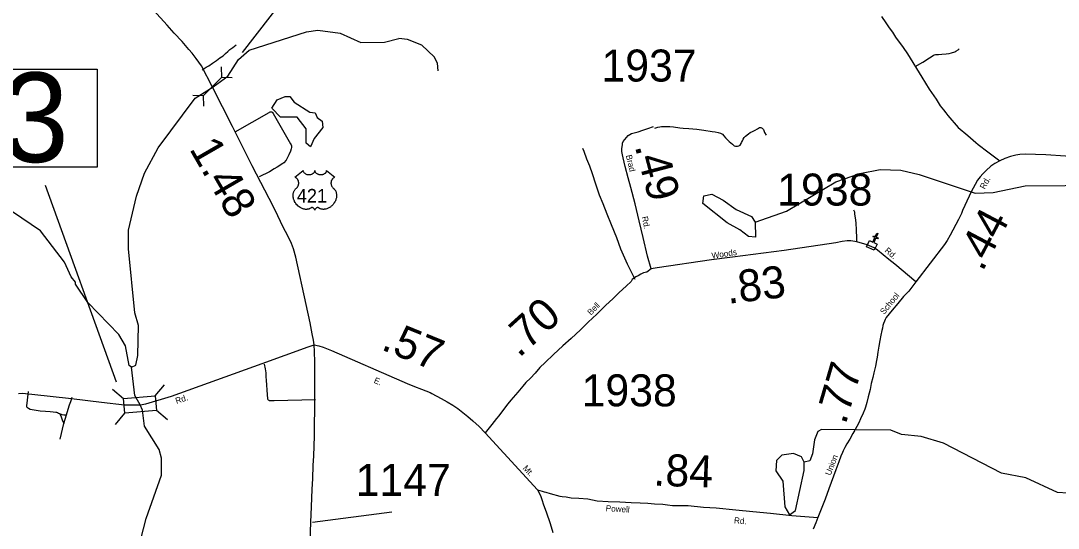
# Model space of a CAD drawing. Extents: x 2093524 to 2270757, y 289120 to 570408.
# Drawn here: x 2218962 to 2235181, y 421724 to 429658 of the extents above; entities that cross this region are included whole.
import ezdxf

# ---------------------------------------------------------------- set-up
doc = ezdxf.new("R2010")
doc.units = 0
for name, color, linetype in [('Exist Cultural Church CELL', 7, 'Continuous'), ('Exist Hydrographic Creek Single Shore', 7, 'Continuous'), ('Exist Hydrographic Misc Water Feature', 7, 'Continuous'), ('Exist Hydrographic Pond Under 1500 Sq Ft', 7, 'Continuous'), ('Exist Road Non-System Type 51', 7, 'Continuous'), ('Exist Road Primary US Attributed', 7, 'Continuous'), ('Exist Road Primary US Mileage Hundredths English Label', 7, 'Continuous'), ('Exist Road Primary US Shield CELL', 7, 'Continuous'), ('Exist Road Primary US Shield Number Label', 7, 'Continuous'), ('Exist Road Primary US Structure Pipe CELL', 7, 'Continuous'), ('Exist Road Primary US Structure Pipe Number Label', 7, 'Continuous'), ('Exist Road Secondary Mileage Hundredths English Label', 7, 'Continuous'), ('Exist Road Secondary Structure Standard Bridge CELL', 7, 'Continuous'), ('Exist Road Secondary Structure Standard Bridge Number Label', 7, 'Continuous'), ('Exist Road Secondary Type 20 Attributed', 7, 'Continuous'), ('Exist Road Secondary Type 51 Attributed', 7, 'Continuous'), ('Exist Road Secondary Type 51 Label', 7, 'Continuous'), ('Exist Road Secondary Type 51 Number Label', 7, 'Continuous')]:
    doc.layers.add(name, color=color, linetype=linetype)

msp = doc.modelspace()

# ---------------------------------------------------------------- linework, layer by layer
at = {"layer": 'Exist Cultural Church CELL'}
msp.add_lwpolyline([(2232231, 426223), (2232283, 426199), (2232315, 426268), (2232286, 426282), (2232292, 426296), (2232321, 426283), (2232347, 426337), (2232361, 426331), (2232336, 426276), (2232365, 426263), (2232358, 426248), (2232329, 426262), (2232297, 426193), (2232350, 426168), (2232305, 426072), (2232186, 426126)], close=True, dxfattribs=at)
at = {"layer": 'Exist Hydrographic Creek Single Shore'}
for points in [[(2220693, 424245), (2220759, 424276), (2220791, 424427), (2220805, 424895), (2220745, 425093), (2220647, 426092), (2220645, 426384), (2220774, 426916), (2220897, 427278), (2221110, 427671), (2221688, 428450), (2221972, 428625), (2222202, 428794), (2222367, 429053), (2222533, 429197), (2223430, 429484), (2223605, 429510), (2223955, 429464), (2224281, 429316), (2224647, 429325), (2224874, 429380)], [(2225486, 428876), (2225477, 428994), (2225426, 429093), (2225233, 429274), (2225008, 429364), (2224874, 429380)], [(2220693, 424245), (2220659, 424269), (2220599, 424575), (2220497, 424751), (2220011, 425256), (2219817, 425538), (2219817, 425571), (2219750, 425654), (2219648, 425886), (2219270, 426376), (2218099, 427167)], [(2220830, 423656), (2220746, 423802), (2220693, 424245)], [(2218324, 417489), (2218794, 418192), (2219207, 418594), (2219652, 419415), (2219767, 419573), (2219958, 419717), (2220073, 419865), (2220418, 420528), (2220666, 420887), (2220925, 421879), (2221162, 422556), (2221161, 422822), (2221126, 422954), (2220899, 423319), (2220868, 423568), (2220830, 423656)], [(2237026, 422309), (2236501, 422411), (2236168, 422392), (2235960, 422333), (2235494, 422261), (2235169, 422284), (2234676, 422513), (2234292, 422586), (2233389, 423054), (2233038, 423159), (2232730, 423188), (2232562, 423260), (2231480, 423269), (2231421, 423237), (2231373, 423104), (2231341, 422885), (2231300, 422777), (2231209, 422759)]]:
    msp.add_lwpolyline(points, dxfattribs=at)
at = {"layer": 'Exist Hydrographic Misc Water Feature'}
msp.add_lwpolyline([(2230445, 426510), (2230935, 426681), (2231706, 427138), (2232080, 427272), (2232396, 427334), (2232721, 427321), (2233005, 427256), (2233882, 426963), (2234165, 426974), (2234664, 427079), (2235288, 427083), (2235429, 427116), (2235612, 427270), (2235711, 427268)], dxfattribs=at)
at = {"layer": 'Exist Hydrographic Pond Under 1500 Sq Ft'}
for points in [[(2223493, 427685), (2223426, 427743), (2223424, 427969), (2223281, 428152), (2223023, 428151), (2222889, 428291), (2222971, 428424), (2223096, 428474), (2223171, 428476), (2223238, 428383), (2223481, 428227), (2223564, 428219), (2223598, 428146), (2223673, 428089), (2223682, 427987), (2223550, 427819), (2223493, 427685)], [(2230445, 426510), (2230447, 426277), (2230339, 426283), (2230205, 426391), (2230004, 426499), (2229627, 426802), (2229642, 426920), (2229767, 426947), (2229943, 426855), (2230144, 426707), (2230386, 426600), (2230445, 426510)], [(2231209, 422759), (2231166, 422842), (2231041, 422891), (2230858, 422865), (2230776, 422781), (2230768, 422624), (2230878, 422458), (2230906, 422057), (2230982, 421934), (2231073, 422001), (2231210, 422625), (2231209, 422759)]]:
    msp.add_lwpolyline(points, dxfattribs=at)
at = {"layer": 'Exist Road Non-System Type 51'}
for p, q in [((2219634, 423363), (2219675, 423498)), ((2219576, 423115), (2219634, 423363)), ((2223525, 421817), (2224763, 421980))]:
    msp.add_line(p, q, dxfattribs=at)
for points in [[(2221797, 428892), (2221863, 428932), (2221904, 428953), (2221958, 428995), (2222024, 429039), (2222075, 429080), (2222125, 429112), (2222163, 429148), (2222197, 429176), (2222231, 429211), (2222280, 429241), (2222330, 429281)], [(2232944, 428944), (2233063, 429012), (2233167, 429078), (2233224, 429117), (2233242, 429125), (2233264, 429129), (2233308, 429129), (2233362, 429134), (2233428, 429140), (2233474, 429147), (2233514, 429157), (2233562, 429171), (2233580, 429182), (2233615, 429204), (2233631, 429220)], [(2222315, 427924), (2222845, 428223), (2222853, 428228), (2222863, 428232), (2222873, 428234), (2222879, 428234), (2222885, 428234), (2222891, 428230), (2222899, 428222), (2222909, 428210), (2223158, 427770), (2223180, 427734), (2223188, 427718), (2223195, 427702), (2223197, 427676), (2223191, 427656), (2223177, 427620), (2223152, 427562), (2223134, 427522), (2223110, 427480), (2223076, 427439), (2223059, 427425), (2222973, 427371), (2222925, 427343), (2222849, 427298), (2222688, 427219)], [(2228874, 427979), (2228877, 427980), (2228923, 427994), (2228953, 428000), (2228979, 428005), (2229045, 428007), (2229107, 428005), (2229165, 428000), (2229268, 427985), (2229316, 427977), (2229405, 427974), (2229529, 427963), (2229641, 427950), (2229772, 427929), (2229816, 427921), (2229864, 427912), (2229900, 427902), (2229930, 427884), (2229954, 427857), (2229980, 427829), (2230037, 427773), (2230087, 427728), (2230113, 427702), (2230138, 427696), (2230169, 427696), (2230189, 427702), (2230207, 427715), (2230225, 427739), (2230229, 427755), (2230243, 427783), (2230256, 427807), (2230270, 427833), (2230290, 427855), (2230338, 427888), (2230365, 427910), (2230403, 427928), (2230445, 427949), (2230481, 427971), (2230495, 427981), (2230513, 427991), (2230525, 427989), (2230531, 427989), (2230551, 427977), (2230561, 427970), (2230573, 427956), (2230591, 427912), (2230616, 427870)], [(2228565, 425614), (2228447, 425851), (2228345, 426088), (2228278, 426266), (2228198, 426467), (2228127, 426632), (2228066, 426794), (2228011, 426933), (2227953, 427106), (2227898, 427266), (2227861, 427386), (2227814, 427493), (2227771, 427613), (2227749, 427663)], [(2232031, 426204), (2232034, 426262), (2232027, 426382), (2232020, 426500), (2232012, 426578), (2232003, 426636), (2231999, 426666), (2231985, 426698)], [(2222766, 424291), (2222781, 424217), (2222791, 424153), (2222796, 424093), (2222798, 424037), (2222814, 423811), (2222818, 423751), (2222820, 423747), (2222826, 423737), (2222830, 423733), (2222838, 423726), (2222846, 423721), (2222870, 423722), (2222924, 423720), (2223568, 423737)], [(2219077, 423860), (2219052, 423639), (2219053, 423631), (2219052, 423625), (2219055, 423617), (2219067, 423611), (2219085, 423600), (2219107, 423588), (2219141, 423582), (2219171, 423574), (2219265, 423561), (2219347, 423557), (2219421, 423550), (2219467, 423546), (2219509, 423541), (2219521, 423538), (2219539, 423533), (2219553, 423525), (2219567, 423519)], [(2219675, 423498), (2219704, 423588), (2219726, 423652), (2219746, 423704), (2219767, 423772)], [(2219567, 423519), (2219605, 423503), (2219611, 423501), (2219635, 423497), (2219675, 423498)], [(2219567, 423519), (2219589, 423483), (2219612, 423421), (2219622, 423395), (2219634, 423363)]]:
    msp.add_lwpolyline(points, dxfattribs=at)
at = {"layer": 'Exist Road Primary US Attributed'}
for points in [[(2223550, 424590), (2223538, 424667), (2223519, 424766), (2223484, 424933), (2223425, 425220), (2223263, 425964), (2223226, 426091), (2223195, 426175), (2223136, 426298), (2223067, 426430), (2222979, 426608), (2222912, 426747), (2222582, 427389), (2222271, 428007), (2221959, 428622), (2221787, 428954), (2221702, 429069), (2221642, 429150), (2221590, 429210), (2221484, 429334), (2221363, 429464), (2221249, 429591), (2221040, 429824), (2219752, 431263)], [(2223487, 421514), (2223498, 421817), (2223510, 422061), (2223519, 422336), (2223527, 422497), (2223536, 422708), (2223543, 422851), (2223554, 423171), (2223560, 423758), (2223560, 424122), (2223561, 424322), (2223556, 424486), (2223550, 424590)]]:
    msp.add_lwpolyline(points, dxfattribs=at)
at = {"layer": 'Exist Road Primary US Shield CELL'}
msp.add_lwpolyline([(2223376, 427315), (2223376, 427310), (2223377, 427303), (2223378, 427300), (2223381, 427294), (2223386, 427286), (2223393, 427279), (2223401, 427273), (2223406, 427270), (2223415, 427265), (2223425, 427261), (2223436, 427257), (2223447, 427255), (2223459, 427254), (2223472, 427254), (2223485, 427255), (2223499, 427257), (2223506, 427259), (2223514, 427262), (2223521, 427265), (2223528, 427269), (2223534, 427273), (2223539, 427276), (2223546, 427283), (2223552, 427289), (2223554, 427293), (2223556, 427297), (2223559, 427305), (2223559, 427308), (2223560, 427315), (2223560, 427309), (2223561, 427306), (2223562, 427302), (2223563, 427298), (2223566, 427293), (2223569, 427288), (2223575, 427281), (2223578, 427278), (2223582, 427275), (2223590, 427269), (2223601, 427264), (2223606, 427262), (2223611, 427260), (2223617, 427258), (2223624, 427256), (2223631, 427255), (2223638, 427254), (2223645, 427254), (2223650, 427254), (2223657, 427254), (2223664, 427254), (2223670, 427255), (2223678, 427256), (2223684, 427257), (2223691, 427259), (2223698, 427262), (2223704, 427265), (2223712, 427269), (2223719, 427273), (2223724, 427277), (2223729, 427282), (2223734, 427288), (2223738, 427292), (2223740, 427297), (2223742, 427302), (2223743, 427307), (2223744, 427312), (2223744, 427315), (2223872, 427213), (2223869, 427212), (2223862, 427208), (2223857, 427205), (2223848, 427199), (2223844, 427195), (2223840, 427192), (2223837, 427188), (2223834, 427184), (2223830, 427179), (2223827, 427174), (2223824, 427168), (2223821, 427163), (2223817, 427153), (2223815, 427147), (2223814, 427141), (2223813, 427130), (2223812, 427124), (2223812, 427119), (2223812, 427113), (2223813, 427108), (2223814, 427102), (2223815, 427097), (2223817, 427091), (2223819, 427084), (2223822, 427077), (2223827, 427065), (2223835, 427054), (2223840, 427048), (2223846, 427042), (2223854, 427036), (2223858, 427032), (2223863, 427027), (2223871, 427017), (2223874, 427013), (2223878, 427008), (2223881, 427003), (2223884, 426998), (2223886, 426993), (2223891, 426982), (2223894, 426971), (2223895, 426965), (2223898, 426953), (2223899, 426947), (2223900, 426934), (2223900, 426919), (2223899, 426905), (2223896, 426889), (2223894, 426879), (2223890, 426867), (2223887, 426857), (2223881, 426843), (2223876, 426832), (2223869, 426820), (2223865, 426812), (2223859, 426804), (2223852, 426795), (2223845, 426785), (2223835, 426775), (2223827, 426767), (2223817, 426758), (2223811, 426753), (2223803, 426746), (2223791, 426738), (2223779, 426732), (2223769, 426727), (2223760, 426723), (2223749, 426718), (2223730, 426713), (2223723, 426712), (2223715, 426711), (2223707, 426710), (2223700, 426709), (2223690, 426709), (2223680, 426710), (2223670, 426711), (2223661, 426713), (2223650, 426717), (2223641, 426720), (2223632, 426725), (2223616, 426735), (2223611, 426737), (2223608, 426738), (2223602, 426738), (2223597, 426737), (2223591, 426735), (2223587, 426733), (2223582, 426730), (2223579, 426727), (2223574, 426723), (2223571, 426719), (2223569, 426716), (2223564, 426709), (2223563, 426706), (2223561, 426702), (2223560, 426695), (2223558, 426703), (2223555, 426709), (2223553, 426713), (2223550, 426717), (2223545, 426722), (2223541, 426726), (2223536, 426730), (2223531, 426733), (2223527, 426735), (2223523, 426737), (2223519, 426738), (2223515, 426738), (2223512, 426738), (2223507, 426737), (2223502, 426733), (2223496, 426729), (2223490, 426726), (2223483, 426722), (2223478, 426719), (2223471, 426717), (2223464, 426714), (2223456, 426712), (2223448, 426711), (2223441, 426710), (2223433, 426709), (2223426, 426709), (2223419, 426709), (2223412, 426709), (2223405, 426710), (2223395, 426712), (2223387, 426713), (2223378, 426716), (2223370, 426718), (2223360, 426722), (2223349, 426727), (2223340, 426731), (2223328, 426739), (2223313, 426749), (2223301, 426758), (2223293, 426766), (2223281, 426778), (2223274, 426786), (2223262, 426801), (2223255, 426811), (2223250, 426819), (2223244, 426832), (2223240, 426839), (2223235, 426851), (2223231, 426861), (2223228, 426871), (2223226, 426877), (2223224, 426888), (2223222, 426896), (2223221, 426907), (2223220, 426918), (2223220, 426929), (2223220, 426937), (2223221, 426948), (2223223, 426958), (2223225, 426967), (2223227, 426974), (2223229, 426982), (2223233, 426991), (2223237, 427000), (2223241, 427007), (2223246, 427014), (2223252, 427021), (2223258, 427028), (2223265, 427034), (2223271, 427039), (2223279, 427047), (2223283, 427051), (2223287, 427057), (2223291, 427063), (2223294, 427068), (2223298, 427076), (2223300, 427081), (2223303, 427090), (2223305, 427096), (2223306, 427104), (2223307, 427111), (2223307, 427120), (2223307, 427128), (2223306, 427137), (2223305, 427145), (2223303, 427153), (2223299, 427161), (2223296, 427168), (2223292, 427176), (2223286, 427184), (2223280, 427190), (2223275, 427196), (2223269, 427200), (2223264, 427204), (2223257, 427208), (2223251, 427211), (2223247, 427212)], close=True, dxfattribs=at)
at = {"layer": 'Exist Road Primary US Structure Pipe CELL'}
for p, q in [((2222097, 428937), (2222101, 428770)), ((2221819, 428491), (2222101, 428770)), ((2222267, 428765), (2222101, 428770)), ((2221653, 428496), (2221819, 428491)), ((2221823, 428324), (2221819, 428491))]:
    msp.add_line(p, q, dxfattribs=at)
at = {"layer": 'Exist Road Primary US Structure Pipe Number Label'}
msp.add_line((2222427, 429161), (2223961, 431142), dxfattribs=at)
at = {"layer": 'Exist Road Secondary Structure Standard Bridge CELL'}
for p, q in [((2221064, 423795), (2221209, 423968)), ((2220396, 423897), (2220570, 423752)), ((2220445, 423347), (2220591, 423521)), ((2221084, 423569), (2221258, 423424))]:
    msp.add_line(p, q, dxfattribs=at)
msp.add_lwpolyline([(2220570, 423752), (2221064, 423796), (2221084, 423565), (2220591, 423521)], close=True, dxfattribs=at)
at = {"layer": 'Exist Road Secondary Structure Standard Bridge Number Label'}
msp.add_line((2220457, 424009), (2219350, 427085), dxfattribs=at)
msp.add_lwpolyline([(2217579, 428899), (2220156, 428899), (2220156, 427370), (2217579, 427370)], close=True, dxfattribs=at)
at = {"layer": 'Exist Road Secondary Type 20 Attributed'}
msp.add_lwpolyline([(2228815, 425782), (2228758, 425978), (2228690, 426271), (2228631, 426530), (2228568, 426798), (2228501, 427049), (2228458, 427203), (2228411, 427380), (2228380, 427514), (2228369, 427564), (2228361, 427616), (2228357, 427638), (2228360, 427660), (2228367, 427720), (2228371, 427744), (2228378, 427769), (2228406, 427800), (2228430, 427832), (2228458, 427863), (2228511, 427895), (2228616, 427923), (2228686, 427947), (2228763, 427972), (2228854, 428003)], dxfattribs=at)
at = {"layer": 'Exist Road Secondary Type 51 Attributed'}
msp.add_line((2226222, 423218), (2227039, 422325), dxfattribs=at)
for points in [[(2232418, 429726), (2232486, 429628), (2232537, 429549), (2232588, 429479), (2232636, 429404), (2232755, 429241), (2232824, 429139), (2233051, 428775), (2233161, 428590), (2233270, 428433), (2233337, 428330), (2233385, 428264), (2233422, 428220), (2233454, 428175), (2233615, 427988), (2233767, 427865), (2233893, 427757), (2233930, 427725), (2234078, 427611), (2234269, 427467)], [(2235771, 427517), (2235505, 427531), (2235294, 427540), (2234986, 427560), (2234663, 427572), (2234582, 427565), (2234517, 427556), (2234437, 427536), (2234348, 427504), (2234269, 427467)], [(2234269, 427467), (2234188, 427425), (2234127, 427386), (2234055, 427316), (2234003, 427265), (2233962, 427218), (2233918, 427165), (2233812, 426974), (2233786, 426914), (2233682, 426690), (2233668, 426646), (2233623, 426553), (2233493, 426306), (2233446, 426224), (2233401, 426158), (2232956, 425579)], [(2232956, 425579), (2232625, 425853), (2232531, 425927), (2232355, 426071), (2232301, 426107), (2232193, 426156), (2232031, 426204), (2231939, 426216), (2231879, 426215), (2231803, 426206), (2231703, 426187), (2230898, 426065), (2230735, 426046), (2230090, 425961), (2229761, 425922), (2228910, 425796), (2228815, 425782)], [(2228815, 425782), (2228749, 425730), (2228700, 425716), (2228654, 425695), (2228614, 425672), (2228578, 425656), (2228520, 425615), (2228504, 425584), (2228426, 425509), (2228315, 425412), (2228223, 425317), (2228105, 425209), (2227970, 425072), (2227831, 424944), (2227712, 424828), (2227567, 424689), (2227438, 424574), (2227289, 424438), (2227158, 424313), (2227077, 424235), (2227004, 424150), (2226930, 424072), (2226859, 424001), (2226813, 423947), (2226732, 423854), (2226661, 423770), (2226625, 423729), (2226576, 423667), (2226509, 423581), (2226435, 423484), (2226398, 423442), (2226325, 423347), (2226222, 423218)], [(2232956, 425579), (2232843, 425429), (2232761, 425345), (2232672, 425240), (2232583, 425131), (2232492, 425017), (2232475, 424986), (2232465, 424962), (2232451, 424924), (2232437, 424894), (2232432, 424854), (2232424, 424814), (2232410, 424742), (2232393, 424658), (2232374, 424572), (2232363, 424476), (2232349, 424400), (2232340, 424346), (2232322, 424260), (2232299, 424154), (2232284, 424079), (2232259, 423989), (2232240, 423893), (2232212, 423779), (2232189, 423691), (2232168, 423619), (2232158, 423584), (2232133, 423524), (2232091, 423436), (2232064, 423370), (2232001, 423259), (2231971, 423207), (2231922, 423117), (2231877, 423044), (2231847, 422986), (2231820, 422932), (2231810, 422908), (2231784, 422850), (2231751, 422760), (2231702, 422635), (2231594, 422338), (2231538, 422180), (2231453, 421972), (2231424, 421890)], [(2220830, 423656), (2220920, 423670), (2221317, 423787), (2222738, 424300), (2223457, 424562), (2223550, 424590)], [(2223550, 424590), (2223621, 424578), (2223691, 424554), (2223820, 424503), (2224922, 424021), (2225002, 423988), (2225118, 423941), (2225229, 423898), (2225363, 423845), (2225387, 423829), (2225536, 423750), (2225626, 423701), (2225718, 423646), (2225793, 423594), (2225871, 423535), (2225952, 423470), (2226032, 423401), (2226131, 423314), (2226222, 423218)], [(2218925, 423832), (2218983, 423834), (2219138, 423821), (2219753, 423753), (2220223, 423693), (2220582, 423656), (2220661, 423651), (2220743, 423651), (2220830, 423656)], [(2227039, 422325), (2227072, 422265), (2227093, 422223), (2227107, 422171), (2227135, 422090), (2227177, 421981), (2227236, 421799), (2227278, 421659)], [(2227039, 422325), (2227113, 422305), (2227147, 422292), (2227173, 422286), (2227240, 422269), (2227390, 422227), (2227426, 422219), (2227489, 422213), (2227569, 422199), (2227688, 422192), (2227828, 422185), (2227975, 422153), (2228144, 422144), (2228328, 422136), (2228506, 422125), (2228647, 422119), (2228767, 422114), (2228868, 422106), (2229000, 422098), (2229074, 422090), (2229153, 422081), (2229397, 422080), (2229635, 422052), (2229834, 422044), (2230139, 422013), (2230405, 421988), (2230685, 421960), (2231017, 421925), (2231424, 421890)], [(2231424, 421890), (2231393, 421809), (2231352, 421709)]]:
    msp.add_lwpolyline(points, dxfattribs=at)

# ---------------------------------------------------------------- texts
at = {"layer": 'Exist Road Primary US Mileage Hundredths English Label'}
msp.add_text('1.48', height=500, rotation=300.0019, dxfattribs=at).set_placement((2221589, 427657))
at = {"layer": 'Exist Road Primary US Shield Number Label'}
msp.add_text('421', height=212.5, dxfattribs=at).set_placement((2223277, 426816))
at = {"layer": 'Exist Road Secondary Mileage Hundredths English Label'}
for s, rotation, p in [('.49', 284.7536, (2228558, 427700)), ('.44', 62.2323, (2233995, 425723)), ('.83', 6.7461, (2230018, 425232)), ('.70', 42.2702, (2226751, 424378)), ('.57', 337.8634, (2224579, 424524)), ('.77', 73.6688, (2231856, 423332)), ('.84', 357.9892, (2228848, 422391))]:
    msp.add_text(s, height=500, rotation=rotation, dxfattribs=at).set_placement(p)
at = {"layer": 'Exist Road Secondary Structure Standard Bridge Number Label'}
msp.add_text('13', height=1400, dxfattribs=at).set_placement((2217630, 427449))
at = {"layer": 'Exist Road Secondary Type 51 Label'}
for s, rotation, p in [('Brad', 282.9601, (2228421, 427552)), ('Rd.', 61.3753, (2234032, 427016)), ('Rd.', 282.6202, (2228669, 426590)), ('Woods', 8.8883, (2229771, 425937)), ('Rd.', 319.592, (2232459, 426052)), ('Bell', 45.4472, (2227876, 425047)), ('School', 50.6786, (2232459, 425058)), ('E.', 337.7238, (2224474, 424000)), ('Rd.', 18.4561, (2221398, 423667)), ('Union', 69.0831, (2231622, 422541)), ('Mt.', 312.4533, (2226803, 422656)), ('Powell', 356.6435, (2228105, 421990)), ('Rd.', 354.7992, (2230109, 421803))]:
    msp.add_text(s, height=95, rotation=rotation, dxfattribs=at).set_placement(p)
at = {"layer": 'Exist Road Secondary Type 51 Number Label'}
for s, p in [('1937', (2228040, 428708)), ('1938', (2230788, 426769)), ('1938', (2227730, 423630)), ('1147', (2224198, 422230))]:
    msp.add_text(s, height=500, dxfattribs=at).set_placement(p)

doc.saveas('drawing.dxf')
